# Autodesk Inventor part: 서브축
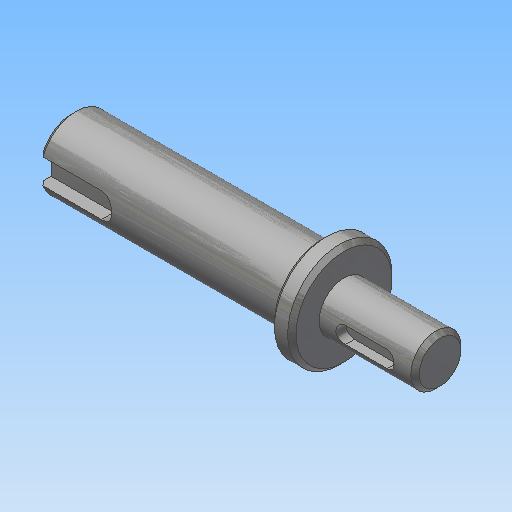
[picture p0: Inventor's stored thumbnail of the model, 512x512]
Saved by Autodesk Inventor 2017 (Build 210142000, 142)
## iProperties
Created: 2018-09
Part Number: 서브축
Document SubType Name: Modeling
Density: 7.86 g/cm^3
Material: 강철, 연강
Appearance: 강철
Mass: 142.801 g
Surface Area: 54.794 cm^2
Volume: 18.1681 cm^3
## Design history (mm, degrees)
sketch "스케치1"
  geometry: L1 (-18.818, -7)-(-18.818, 7) reference; L2 (-41.331, -13.5)-(-41.331, 13.5) reference; L3 (-46.5, 12.249)-(-46.5, -12.249) reference; L4 (-18.331, 0)-(-106.5, 0); L5 (-18.331, 0)-(-18.331, -6); L6 (-18.331, -6)-(-41.331, -6); L7 (-41.331, -12.5)-(-46.5, -12.5); L8 (-46.5, -8.5)-(-106.5, -8.5); L9 (-106.5, -8.5)-(-106.5, 0); L10 (-46.5, -8.5)-(-46.5, -12.5); L11 (-41.331, -6)-(-41.331, -12.5); 2 further points
  constraints: 17 end point, 5 point on line, 3 parallel, 3 perpendicular, 2 collinear, 1 midpoint
  dimensions: "d0" = 23 distance between parallel lines of L2 L5; "d1" = 12 diameter of L6 L4; "d2" = 25 diameter of L7 L4; "d3" = 17 diameter of L8 L4; "d4" = 60 distance of L8.start L8.end
revolve "회전1" sketch "스케치1" stored, may be unused: angle "d5" = 90 deg
chamfer "모따기1" distance "d6" = 1; stored, may be unused: second distance "d7" = 2, angle "d8" = 45 deg
node "작업 평면1"
sketch "스케치2"
  geometry: L1 (11.5, 5)-(11.5, -5) reference; L2 (-5.5, -2)-(4.5, -2); L3 (4.5, 2)-(-5.5, 2); A1 r 2 centre (4.5, 0) between (4.5, -2) and (4.5, 2); A2 r 2 centre (-5.5, 0) between (-5.5, 2) and (-5.5, -2); 2 further points
  constraints: 4 end point, 4 point on circle, 4 tangent, 2 centre point, 1 horizontal alignment, 1 midpoint, 1 parallel, 1 perpendicular
  dimensions: "d9" = 4 distance between parallel lines of L2 L3; "d10" = 14 dimension on A1 A2; "d11" = 5 distance edge to line of A1 L1
extrude "돌출1" cut sketch "스케치2" distance "d12" = 2.5; taper "d13" = 0 deg
node "작업 평면2"
sketch "스케치3"
  geometry: L1 (-30, -7.5)-(-30, 7.5) reference; L2 (-30, 3)-(-15, 3); L3 (-15, -3)-(-30, -3); A1 r 3 centre (-15, 0) between (-15, -3) and (-15, 3); 2 further points
  constraints: 4 end point, 2 perpendicular, 2 point on circle, 2 point on line, 2 tangent, 1 centre point, 1 horizontal alignment, 1 midpoint
  dimensions: "d14" = 6 distance between parallel lines of L3 L2; "d15" = 18 dimension on A1 L1
extrude "돌출2" cut sketch "스케치3" distance "d16" = 3.5; taper "d17" = 0 deg
node "솔리드1"
node "참조1"
node "참조2"
node "참조3"
